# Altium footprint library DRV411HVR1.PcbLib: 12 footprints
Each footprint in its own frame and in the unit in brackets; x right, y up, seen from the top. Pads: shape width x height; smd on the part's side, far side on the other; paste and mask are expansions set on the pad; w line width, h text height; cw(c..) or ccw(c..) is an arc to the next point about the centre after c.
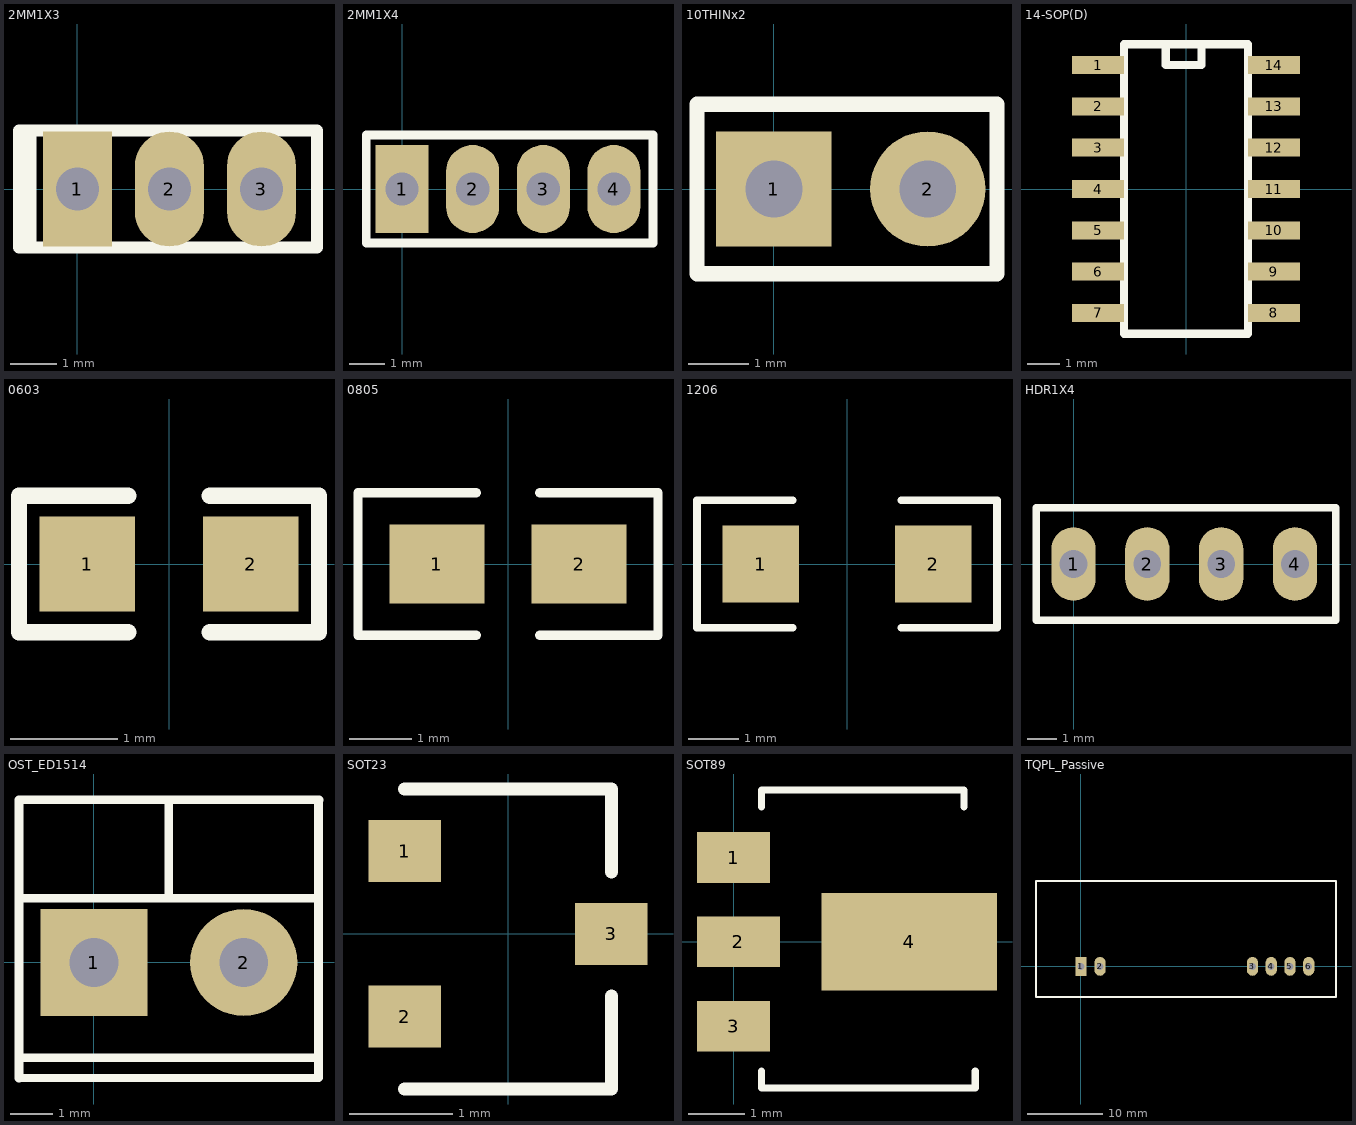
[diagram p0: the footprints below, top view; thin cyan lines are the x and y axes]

## 2MM1X3 [mm]
pads (3):
  rect 1.5x2.5 hole 0.94: 1(0,0)
  oval 1.5x2.5 hole 0.94: 2(2,0) 3(4,0)
TopOverlay:
  lines w0.254: -1.016,-1.27 -1.016,1.27 ; -1.27,-1.27 -1.27,1.27 5.207,1.27 5.207,-1.27 -1.27,-1.27

## 2MM1X4 [mm]
pads (4):
  rect 1.5x2.5 hole 0.94: 1(0,0)
  oval 1.5x2.5 hole 0.94: 2(2,0) 3(4,0) 4(6,0)
TopOverlay:
  lines w0.254: -1.016,-1.524 7.112,-1.524 7.112,1.524 -1.016,1.524 -1.016,-1.524

## 10THINx2 [mil]
pads (2):
  rect 75x75 hole 37: 1(0,0)
  round 75 hole 37: 2(100,0)
TopOverlay:
  lines w10: -50,-55 -50,55 145,55 145,-55 -50,-55

## 14-SOP(D) [mm]
pads (14):
  rect 1.6x0.55 smd: 1(-2.7,3.81) 2(-2.7,2.54) 3(-2.7,1.27) 4(-2.7,0) 5(-2.7,-1.27) 6(-2.7,-2.54) 7(-2.7,-3.81) 8(2.7,-3.81) 9(2.7,-2.54) 10(2.7,-1.27) 11(2.7,0) 12(2.7,1.27) 13(2.7,2.54) 14(2.7,3.81)
TopOverlay:
  lines w0.254: -0.626,4.31 -0.626,3.81 0.474,3.81 0.474,4.31 ; -1.905,-4.445 1.905,-4.445 1.905,4.445 -1.905,4.445 -1.905,-4.445

## 0603 [mil]
pads (2):
  rect 35x35 smd: 1(-30,0) 2(30,0)
TopOverlay:
  lines w6: -15,-25 -55,-25 -55,25 -15,25 ; 15,-25 55,-25 55,25 15,25

## 0805 [mil]
pads (2):
  rect 60x50 smd: 1(-45,0.06) 2(45,0.06)
TopOverlay:
  lines w6: -20,-44.94 -95,-44.94 -95,45.06 -20,45.06 ; 20,-44.94 95,-44.94 95,45.06 20,45.06

## 1206 [mil]
pads (2):
  rect 60x60 smd: 1(-67.5,0) 2(67.5,0)
TopOverlay:
  lines w6: -42.5,-50 -117.5,-50 -117.5,50 -42.5,50 ; 42.5,-50 117.5,-50 117.5,50 42.5,50

## HDR1X4 [mm]
pads (4):
  oval 1.5x2.5 hole 0.94: 1(0,0) 2(2.5,0) 3(5,0) 4(7.5,0)
TopOverlay:
  lines w0.254: -1.27,-1.905 8.89,-1.905 8.89,1.905 -1.27,1.905 -1.27,-1.905

## OST_ED1514 [mm]
pads (2):
  rect 2.5x2.5 hole 1.143: 1(0,-0.013)
  round 2.5 hole 1.143: 2(3.5,-0.013)
TopOverlay:
  lines w0.203: -1.75,-2.236 5.22,-2.236 ; -1.75,1.487 5.232,1.486 ; 1.75,1.487 1.75,3.787 ; 5.232,-2.705 -1.75,-2.713 -1.75,3.787 5.258,3.785 ; 5.245,-2.705 5.245,3.787

## SOT23 [mm]
pads (3):
  rect 0.7x0.6 smd: 1(-1,0.8) 2(-1,-0.8) 3(1,0)
TopOverlay:
  lines w0.127: -1,-1.5 1,-1.5 1,-0.6 ; -1,1.4 1,1.4 1,0.6

## SOT89 [mm]
pads (4):
  rect 1.3x0.9 smd: 1(0,1.5) 3(0,-1.5)
  rect 1.475x0.9 smd: 2(0.088,0)
  rect 3.125x1.733 smd: 4(3.125,0)
TopOverlay:
  lines w0.127: 0.5,-2.3 0.5,-2.6 4.3,-2.6 4.3,-2.3 ; 0.5,2.4 0.5,2.7 4.1,2.7 4.1,2.4

## TQPL_Passive [mm] "Passive Current sensor with Hall and Coil only"
height 25
pads (6):
  rect 1.5x2.5 hole 0.94: 1(0,0)
  oval 1.5x2.5 hole 0.94: 2(2.54,0) 3(22.86,0) 4(25.36,0) 5(27.86,0) 6(30.36,0)
TopOverlay:
  lines w0.254: -6,-4.1 -6,11.4 34,11.4 34,-4.1 -6,-4.1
